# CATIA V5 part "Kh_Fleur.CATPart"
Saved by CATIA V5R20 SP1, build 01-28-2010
Part number: Fleur
Bounding box of the stored display mesh (mm): x 0 to 20, y -33.167 to 33.167, z -30.751 to 33.99
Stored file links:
  G:\Khaled_CFAO_2011\SIL\SIL_GR1\tmerino\Khaled\CAD_Thinkmotion\Kh_Fleur.CATPart
  G:\Khaled_CFAO_2011\SIL\SIL_GR1\tmerino\Khaled\CAD_Thinkmotion\Kh_Catalog.CATMaterial
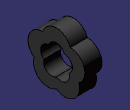
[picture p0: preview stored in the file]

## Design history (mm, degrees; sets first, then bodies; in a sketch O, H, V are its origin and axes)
Body1 (main body), material "Caoutchouc"
  Sketch1 on yz-plane, origin (0, 0, 0), H (0, 1, 0), V (0, 0, 1)
    arc A1 centre (0, 17) radius 17 from (16.168, 22.2533) to (-16.168, 22.2533) ccw
    point P2 (0, 0)
    arc A2 centre (-16.168, 5.2533) radius 17 from (-16.168, 22.2533) to (-26.1603, -8.5) ccw
    arc A3 centre (16.168, 5.2533) radius 17 from (26.1603, -8.5) to (16.168, 22.2533) ccw
    arc A4 centre (9.9923, -13.7533) radius 17 from (0, -27.5066) to (26.1603, -8.5) ccw
    arc A5 centre (-9.9923, -13.7533) radius 17 from (-26.1603, -8.5) to (0, -27.5066) ccw
    arc A6 centre (0, 9.5) radius 9.5 from (9.035, 12.4357) to (-9.035, 12.4357) ccw
    arc A7 centre (-9.035, 2.9357) radius 9.5 from (-9.035, 12.4357) to (-14.619, -4.75) ccw
    arc A8 centre (-5.584, -7.6857) radius 9.5 from (-14.619, -4.75) to (0, -15.3713) ccw
    arc A9 centre (9.035, 2.9357) radius 9.5 from (14.619, -4.75) to (9.035, 12.4357) ccw
    arc A10 centre (5.584, -7.6857) radius 9.5 from (0, -15.3713) to (14.619, -4.75) ccw
    distance A6 H = 0
  Pad1: profile Sketch1, direction (1, 0, 0), length 20
  Sketch2 on xy-plane, origin (0, 0, 0), H (1, 0, 0), V (0, 1, 0)
    axis line L1 (-10, 0) -> (40, 0)
    point P1 (-10, 0)
    coincidence: P1 H
    horizontal: L1 H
